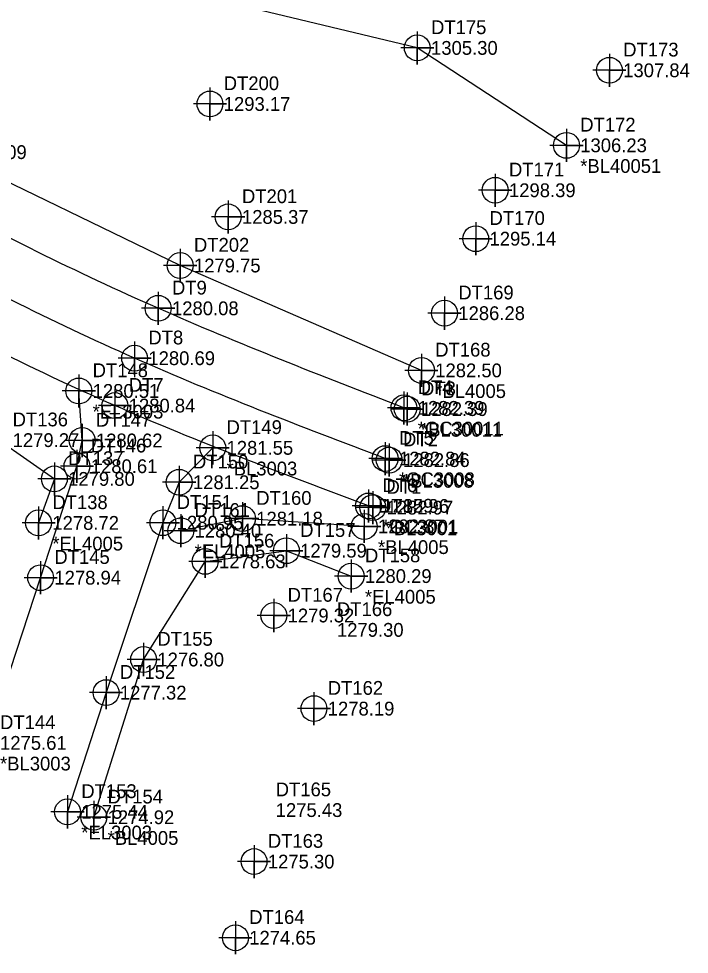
# Model space of a CAD drawing. Extents: x 1391270 to 1392151, y 960049 to 960667.
# Drawn here: x 1391845.8 to 1391967.4, y 960049.1 to 960218.7 of the extents above; entities that cross this region are included whole.
import ezdxf

# ---------------------------------------------------------------- set-up
doc = ezdxf.new("R2010")
doc.units = 0
for name, color, linetype in [('Exist DTM Breakline', 7, 'Continuous'), ('Exist DTM Breakline Cogo Comment', 7, 'Continuous'), ('Exist DTM Breakline Cogo Elevation', 7, 'Continuous'), ('Exist DTM Breakline Cogo Number', 7, 'Continuous'), ('Exist DTM Breakline Cogo Point CELL', 7, 'Continuous'), ('Exist DTM Crownline', 7, 'Continuous'), ('Exist DTM Crownline Cogo Comment', 7, 'Continuous'), ('Exist DTM Crownline Cogo Elevation', 7, 'Continuous'), ('Exist DTM Crownline Cogo Number', 7, 'Continuous'), ('Exist DTM Crownline Cogo Point CELL', 7, 'Continuous'), ('Exist DTM Regular Point CELL', 7, 'Continuous'), ('Exist DTM Regular Point Cogo Elevation', 7, 'Continuous'), ('Exist DTM Regular Point Cogo Number', 7, 'Continuous'), ('Exist Roads EOP', 7, 'Continuous'), ('Exist Roads EOP Cogo Comment', 7, 'Continuous'), ('Exist Roads EOP Cogo Elevation', 7, 'Continuous'), ('Exist Roads EOP Cogo Number', 7, 'Continuous'), ('Exist Roads EOP Cogo Point CELL', 7, 'Continuous'), ('Exist Roads EOP Other', 7, 'Continuous'), ('Exist Roads EOP Other Cogo Comment', 7, 'Continuous'), ('Exist Roads EOP Other Cogo Elevation', 7, 'Continuous'), ('Exist Roads EOP Other Cogo Number', 7, 'Continuous'), ('Exist Roads EOP Other Cogo Point CELL', 7, 'Continuous'), ('Exist Vegetation Shrub Cogo Elevation', 7, 'Continuous'), ('Exist Vegetation Shrub Cogo Number', 7, 'Continuous'), ('Exist Vegetation Tree Cogo Elevation', 7, 'Continuous'), ('Exist Vegetation Tree Cogo Number', 7, 'Continuous')]:
    doc.layers.add(name, color=color, linetype=linetype)

msp = doc.modelspace()

# ---------------------------------------------------------------- linework, layer by layer
at = {"layer": 'Exist DTM Breakline'}
for points in [[(1391945.147, 960195.757), (1391918.09, 960213.421), (1391881.206, 960222.292), (1391849.896, 960235.631), (1391826.517, 960251.571), (1391802.004, 960268.368), (1391783.721, 960280.05), (1391763.211, 960305.363), (1391726.912, 960330.123), (1391710.789, 960346.476), (1391703.438, 960384.306)], [(1391918.848, 960154.955), (1391875.094, 960173.971), (1391832.683, 960194.523), (1391807.232, 960209.528), (1391789.699, 960221.943), (1391750.487, 960246.736), (1391714.022, 960278.792), (1391697.218, 960295.108)], [(1391783.595, 960167.857), (1391809.479, 960158.717), (1391842.214, 960142.313), (1391852.279, 960135.283), (1391849.414, 960127.307)], [(1391908.471, 960126.669), (1391886.387, 960128.086), (1391875.205, 960125.894)], [(1391859.44, 960073.944), (1391868.463, 960102.54), (1391879.641, 960120.333), (1391894.357, 960122.271), (1391906.105, 960117.666)]]:
    msp.add_lwpolyline(points, dxfattribs=at)
at = {"layer": 'Exist DTM Breakline Cogo Point CELL'}
for points in [[(1391918.09, 960216.421), (1391918.09, 960210.421), (1391918.09, 960213.421), (1391921.09, 960213.421), (1391915.09, 960213.421)], [(1391945.147, 960198.757), (1391945.147, 960192.757), (1391945.147, 960195.757), (1391948.147, 960195.757), (1391942.147, 960195.757)], [(1391875.094, 960176.971), (1391875.094, 960170.971), (1391875.094, 960173.971), (1391878.094, 960173.971), (1391872.094, 960173.971)], [(1391918.848, 960157.955), (1391918.848, 960151.955), (1391918.848, 960154.955), (1391921.848, 960154.955), (1391915.848, 960154.955)], [(1391852.279, 960138.283), (1391852.279, 960132.283), (1391852.279, 960135.283), (1391855.279, 960135.283), (1391849.279, 960135.283)], [(1391849.414, 960130.307), (1391849.414, 960124.307), (1391849.414, 960127.307), (1391852.414, 960127.307), (1391846.414, 960127.307)], [(1391886.387, 960131.086), (1391886.387, 960125.086), (1391886.387, 960128.086), (1391889.387, 960128.086), (1391883.387, 960128.086)], [(1391908.471, 960129.669), (1391908.471, 960123.669), (1391908.471, 960126.669), (1391911.471, 960126.669), (1391905.471, 960126.669)], [(1391875.205, 960128.894), (1391875.205, 960122.894), (1391875.205, 960125.894), (1391878.205, 960125.894), (1391872.205, 960125.894)], [(1391894.357, 960125.271), (1391894.357, 960119.271), (1391894.357, 960122.271), (1391897.357, 960122.271), (1391891.357, 960122.271)], [(1391879.641, 960123.333), (1391879.641, 960117.333), (1391879.641, 960120.333), (1391882.641, 960120.333), (1391876.641, 960120.333)], [(1391906.105, 960120.666), (1391906.105, 960114.666), (1391906.105, 960117.666), (1391909.105, 960117.666), (1391903.105, 960117.666)], [(1391868.463, 960105.54), (1391868.463, 960099.54), (1391868.463, 960102.54), (1391871.463, 960102.54), (1391865.463, 960102.54)], [(1391859.44, 960076.944), (1391859.44, 960070.944), (1391859.44, 960073.944), (1391862.44, 960073.944), (1391856.44, 960073.944)]]:
    msp.add_lwpolyline(points, dxfattribs=at)
for centre in [(1391918.09, 960213.421), (1391945.147, 960195.757), (1391875.094, 960173.971), (1391918.848, 960154.955), (1391852.279, 960135.283), (1391849.414, 960127.307), (1391886.387, 960128.086), (1391875.205, 960125.894), (1391908.471, 960126.669), (1391894.357, 960122.271), (1391879.641, 960120.333), (1391906.105, 960117.666), (1391868.463, 960102.54), (1391859.44, 960073.944)]:
    msp.add_circle(centre, 2.344, dxfattribs=at)
at = {"layer": 'Exist DTM Crownline'}
msp.add_line((1391913.011, 960138.693), (1391912.281, 960138.966), dxfattribs=at)
msp.add_spline([(1391912.281, 960138.966), (1391866.83, 960157.169), (1391822.661, 960179.344), (1391780.998, 960205.13), (1391740.996, 960234.086), (1391702.853, 960265.768), (1391666.471, 960297.967)], degree=3, dxfattribs=at)
at = {"layer": 'Exist DTM Crownline Cogo Point CELL'}
for points in [[(1391866.83, 960160.169), (1391866.83, 960154.169), (1391866.83, 960157.169), (1391869.83, 960157.169), (1391863.83, 960157.169)], [(1391912.281, 960141.966), (1391912.281, 960135.966), (1391912.281, 960138.966), (1391915.281, 960138.966), (1391909.281, 960138.966)], [(1391913.011, 960141.693), (1391913.011, 960135.693), (1391913.011, 960138.693), (1391916.011, 960138.693), (1391910.011, 960138.693)]]:
    msp.add_lwpolyline(points, dxfattribs=at)
for centre in [(1391866.83, 960157.169), (1391912.281, 960138.966), (1391913.011, 960138.693)]:
    msp.add_circle(centre, 2.344, dxfattribs=at)
at = {"layer": 'Exist DTM Regular Point CELL'}
for points in [[(1391952.934, 960212.364), (1391952.934, 960206.364), (1391952.934, 960209.364), (1391955.934, 960209.364), (1391949.934, 960209.364)], [(1391880.495, 960206.26), (1391880.495, 960200.26), (1391880.495, 960203.26), (1391883.495, 960203.26), (1391877.495, 960203.26)], [(1391932.223, 960190.612), (1391932.223, 960184.612), (1391932.223, 960187.612), (1391935.223, 960187.612), (1391929.223, 960187.612)], [(1391883.798, 960185.78), (1391883.798, 960179.78), (1391883.798, 960182.78), (1391886.798, 960182.78), (1391880.798, 960182.78)], [(1391928.694, 960181.83), (1391928.694, 960175.83), (1391928.694, 960178.83), (1391931.694, 960178.83), (1391925.694, 960178.83)], [(1391923.036, 960168.326), (1391923.036, 960162.326), (1391923.036, 960165.326), (1391926.036, 960165.326), (1391920.036, 960165.326)], [(1391892.081, 960113.522), (1391892.081, 960107.522), (1391892.081, 960110.522), (1391895.081, 960110.522), (1391889.081, 960110.522)], [(1391899.359, 960096.642), (1391899.359, 960090.642), (1391899.359, 960093.642), (1391902.359, 960093.642), (1391896.359, 960093.642)], [(1391888.493, 960068.907), (1391888.493, 960062.907), (1391888.493, 960065.907), (1391891.493, 960065.907), (1391885.493, 960065.907)], [(1391885.115, 960055.102), (1391885.115, 960049.102), (1391885.115, 960052.102), (1391888.115, 960052.102), (1391882.115, 960052.102)]]:
    msp.add_lwpolyline(points, dxfattribs=at)
for centre in [(1391952.934, 960209.364), (1391880.495, 960203.26), (1391932.223, 960187.612), (1391883.798, 960182.78), (1391928.694, 960178.83), (1391923.036, 960165.326), (1391892.081, 960110.522), (1391899.359, 960093.642), (1391888.493, 960065.907), (1391885.115, 960052.102)]:
    msp.add_circle(centre, 2.344, dxfattribs=at)
at = {"layer": 'Exist Roads EOP'}
for p, q in [((1391916.273, 960147.94), (1391915.673, 960148.156)), ((1391910.019, 960130.083), (1391909.259, 960130.384))]:
    msp.add_line(p, q, dxfattribs=at)
for points in [[(1391915.673, 960148.156), (1391871.111, 960166.209), (1391827.705, 960187.765), (1391786.031, 960213.485), (1391746.988, 960241.829), (1391709.378, 960273.178), (1391672.886, 960305.161)], [(1391909.259, 960130.384), (1391863.262, 960148.577), (1391817.991, 960171.223), (1391775.806, 960197.201), (1391735.389, 960227.09), (1391696.713, 960258.946), (1391660.088, 960291.389)]]:
    msp.add_spline(points, degree=3, dxfattribs=at)
at = {"layer": 'Exist Roads EOP Cogo Point CELL'}
for points in [[(1391871.111, 960169.209), (1391871.111, 960163.209), (1391871.111, 960166.209), (1391874.111, 960166.209), (1391868.111, 960166.209)], [(1391863.262, 960151.577), (1391863.262, 960145.577), (1391863.262, 960148.577), (1391866.262, 960148.577), (1391860.262, 960148.577)], [(1391915.673, 960151.156), (1391915.673, 960145.156), (1391915.673, 960148.156), (1391918.673, 960148.156), (1391912.673, 960148.156)], [(1391916.273, 960150.94), (1391916.273, 960144.94), (1391916.273, 960147.94), (1391919.273, 960147.94), (1391913.273, 960147.94)], [(1391909.259, 960133.384), (1391909.259, 960127.384), (1391909.259, 960130.384), (1391912.259, 960130.384), (1391906.259, 960130.384)], [(1391910.019, 960133.083), (1391910.019, 960127.083), (1391910.019, 960130.083), (1391913.019, 960130.083), (1391907.019, 960130.083)]]:
    msp.add_lwpolyline(points, dxfattribs=at)
for centre in [(1391871.111, 960166.209), (1391863.262, 960148.577), (1391915.673, 960148.156), (1391916.273, 960147.94), (1391909.259, 960130.384), (1391910.019, 960130.083)]:
    msp.add_circle(centre, 2.344, dxfattribs=at)
at = {"layer": 'Exist Roads EOP Other'}
for points in [[(1391839.93, 960087.426), (1391849.786, 960117.376), (1391856.383, 960137.584), (1391857.314, 960142.252), (1391856.722, 960151.227)], [(1391881.003, 960140.916), (1391874.905, 960134.676), (1391871.97, 960127.346), (1391861.66, 960096.537), (1391854.663, 960074.923)]]:
    msp.add_lwpolyline(points, dxfattribs=at)
at = {"layer": 'Exist Roads EOP Other Cogo Point CELL'}
for points in [[(1391856.722, 960154.227), (1391856.722, 960148.227), (1391856.722, 960151.227), (1391859.722, 960151.227), (1391853.722, 960151.227)], [(1391857.314, 960145.252), (1391857.314, 960139.252), (1391857.314, 960142.252), (1391860.314, 960142.252), (1391854.314, 960142.252)], [(1391881.003, 960143.916), (1391881.003, 960137.916), (1391881.003, 960140.916), (1391884.003, 960140.916), (1391878.003, 960140.916)], [(1391856.383, 960140.584), (1391856.383, 960134.584), (1391856.383, 960137.584), (1391859.383, 960137.584), (1391853.383, 960137.584)], [(1391874.905, 960137.676), (1391874.905, 960131.676), (1391874.905, 960134.676), (1391877.905, 960134.676), (1391871.905, 960134.676)], [(1391871.97, 960130.346), (1391871.97, 960124.346), (1391871.97, 960127.346), (1391874.97, 960127.346), (1391868.97, 960127.346)], [(1391849.786, 960120.376), (1391849.786, 960114.376), (1391849.786, 960117.376), (1391852.786, 960117.376), (1391846.786, 960117.376)], [(1391861.66, 960099.537), (1391861.66, 960093.537), (1391861.66, 960096.537), (1391864.66, 960096.537), (1391858.66, 960096.537)], [(1391854.663, 960077.923), (1391854.663, 960071.923), (1391854.663, 960074.923), (1391857.663, 960074.923), (1391851.663, 960074.923)]]:
    msp.add_lwpolyline(points, dxfattribs=at)
for centre in [(1391856.722, 960151.227), (1391857.314, 960142.252), (1391881.003, 960140.916), (1391856.383, 960137.584), (1391874.905, 960134.676), (1391871.97, 960127.346), (1391849.786, 960117.376), (1391861.66, 960096.537), (1391854.663, 960074.923)]:
    msp.add_circle(centre, 2.344, dxfattribs=at)

# ---------------------------------------------------------------- texts
at = {"layer": 'Exist DTM Breakline Cogo Comment'}
for s, p in [('*BL40051', (1391947.647, 960190.757)), ('*BL4005', (1391921.348, 960149.955)), ('*EL4005', (1391851.914, 960122.307)), ('*EL4005', (1391877.705, 960120.894)), ('*BL4005', (1391910.971, 960121.669)), ('*EL4005', (1391908.605, 960112.666)), ('*BL4005', (1391861.94, 960068.944))]:
    msp.add_text(s, height=2.5, dxfattribs=at).set_placement(p)
at = {"layer": 'Exist DTM Breakline Cogo Elevation'}
for s, p in [('1305.30', (1391920.59, 960212.171)), ('1277.09', (1391835.183, 960193.273)), ('1306.23', (1391947.647, 960194.507)), ('1279.75', (1391877.594, 960172.721)), ('1282.50', (1391921.348, 960153.705)), ('1279.27', (1391844.714, 960141.063)), ('1279.80', (1391854.779, 960134.033)), ('1278.72', (1391851.914, 960126.057)), ('1281.18', (1391888.887, 960126.836)), ('1282.87', (1391910.971, 960125.419)), ('1280.40', (1391877.705, 960124.644)), ('1279.59', (1391896.857, 960121.021)), ('1278.63', (1391882.141, 960119.083)), ('1280.29', (1391908.605, 960116.416)), ('1276.80', (1391870.963, 960101.29)), ('1274.92', (1391861.94, 960072.694))]:
    msp.add_text(s, height=2.5, dxfattribs=at).set_placement(p)
at = {"layer": 'Exist DTM Breakline Cogo Number'}
for s, p in [('DT175', (1391920.59, 960215.921)), ('DT172', (1391947.647, 960198.257)), ('DT202', (1391877.594, 960176.471)), ('DT168', (1391921.348, 960157.455)), ('DT136', (1391844.714, 960144.813)), ('DT137', (1391854.779, 960137.783)), ('DT160', (1391888.887, 960130.586)), ('DT138', (1391851.914, 960129.807)), ('DT159', (1391910.971, 960129.169)), ('DT161', (1391877.705, 960128.394)), ('DT157', (1391896.857, 960124.771)), ('DT156', (1391882.141, 960122.833)), ('DT158', (1391908.605, 960120.166)), ('DT155', (1391870.963, 960105.04)), ('DT154', (1391861.94, 960076.444))]:
    msp.add_text(s, height=2.5, dxfattribs=at).set_placement(p)
at = {"layer": 'Exist DTM Crownline Cogo Comment'}
for s, p in [('*OC3008', (1391914.781, 960133.966)), ('*BL3008', (1391915.511, 960133.693))]:
    msp.add_text(s, height=2.5, dxfattribs=at).set_placement(p)
at = {"layer": 'Exist DTM Crownline Cogo Elevation'}
for s, p in [('1280.69', (1391869.33, 960155.919)), ('1282.84', (1391914.781, 960137.716)), ('1282.86', (1391915.511, 960137.443))]:
    msp.add_text(s, height=2.5, dxfattribs=at).set_placement(p)
at = {"layer": 'Exist DTM Crownline Cogo Number'}
for s, p in [('DT8', (1391869.33, 960159.669)), ('DT5', (1391914.781, 960141.466)), ('DT2', (1391915.511, 960141.193))]:
    msp.add_text(s, height=2.5, dxfattribs=at).set_placement(p)
at = {"layer": 'Exist DTM Regular Point Cogo Elevation'}
for s, p in [('1307.84', (1391955.434, 960208.114)), ('1293.17', (1391882.995, 960202.01)), ('1298.39', (1391934.723, 960186.362)), ('1285.37', (1391886.298, 960181.53)), ('1295.14', (1391931.194, 960177.58)), ('1286.28', (1391925.536, 960164.076)), ('1278.19', (1391901.859, 960092.392)), ('1275.30', (1391890.993, 960064.657)), ('1274.65', (1391887.615, 960050.852))]:
    msp.add_text(s, height=2.5, dxfattribs=at).set_placement(p)
at = {"layer": 'Exist DTM Regular Point Cogo Number'}
for s, p in [('DT173', (1391955.434, 960211.864)), ('DT200', (1391882.995, 960205.76)), ('DT171', (1391934.723, 960190.112)), ('DT201', (1391886.298, 960185.28)), ('DT170', (1391931.194, 960181.33)), ('DT169', (1391925.536, 960167.826)), ('DT162', (1391901.859, 960096.142)), ('DT163', (1391890.993, 960068.407)), ('DT164', (1391887.615, 960054.602))]:
    msp.add_text(s, height=2.5, dxfattribs=at).set_placement(p)
at = {"layer": 'Exist Roads EOP Cogo Comment'}
for s, p in [('*OC30011', (1391918.173, 960143.156)), ('*BL30011', (1391918.773, 960142.94)), ('*OC3001', (1391911.759, 960125.384)), ('*BL3001', (1391912.519, 960125.083))]:
    msp.add_text(s, height=2.5, dxfattribs=at).set_placement(p)
at = {"layer": 'Exist Roads EOP Cogo Elevation'}
for s, p in [('1280.08', (1391873.611, 960164.959)), ('1280.84', (1391865.762, 960147.327)), ('1282.39', (1391918.173, 960146.906)), ('1282.39', (1391918.773, 960146.69)), ('1282.96', (1391911.759, 960129.134)), ('1282.97', (1391912.519, 960128.833))]:
    msp.add_text(s, height=2.5, dxfattribs=at).set_placement(p)
at = {"layer": 'Exist Roads EOP Cogo Number'}
for s, p in [('DT9', (1391873.611, 960168.709)), ('DT7', (1391865.762, 960151.077)), ('DT4', (1391918.173, 960150.656)), ('DT3', (1391918.773, 960150.44)), ('DT6', (1391911.759, 960132.884)), ('DT1', (1391912.519, 960132.583))]:
    msp.add_text(s, height=2.5, dxfattribs=at).set_placement(p)
at = {"layer": 'Exist Roads EOP Other Cogo Comment'}
for s, p in [('*EL3003', (1391859.222, 960146.227)), ('*BL3003', (1391883.503, 960135.916)), ('*BL3003', (1391842.43, 960082.426)), ('*EL3003', (1391857.163, 960069.923))]:
    msp.add_text(s, height=2.5, dxfattribs=at).set_placement(p)
at = {"layer": 'Exist Roads EOP Other Cogo Elevation'}
for s, p in [('1280.51', (1391859.222, 960149.977)), ('1280.62', (1391859.814, 960141.002)), ('1281.55', (1391883.503, 960139.666)), ('1280.61', (1391858.883, 960136.334)), ('1281.25', (1391877.405, 960133.426)), ('1280.95', (1391874.47, 960126.096)), ('1278.94', (1391852.286, 960116.126)), ('1277.32', (1391864.16, 960095.287)), ('1275.61', (1391842.43, 960086.176)), ('1275.44', (1391857.163, 960073.673))]:
    msp.add_text(s, height=2.5, dxfattribs=at).set_placement(p)
at = {"layer": 'Exist Roads EOP Other Cogo Number'}
for s, p in [('DT148', (1391859.222, 960153.727)), ('DT147', (1391859.814, 960144.752)), ('DT149', (1391883.503, 960143.416)), ('DT146', (1391858.883, 960140.084)), ('DT150', (1391877.405, 960137.176)), ('DT151', (1391874.47, 960129.846)), ('DT145', (1391852.286, 960119.876)), ('DT152', (1391864.16, 960099.037)), ('DT144', (1391842.43, 960089.926)), ('DT153', (1391857.163, 960077.423))]:
    msp.add_text(s, height=2.5, dxfattribs=at).set_placement(p)
at = {"layer": 'Exist Vegetation Shrub Cogo Elevation'}
for s, p in [('1279.32', (1391894.581, 960109.272)), ('1279.30', (1391903.528, 960106.666))]:
    msp.add_text(s, height=2.5, dxfattribs=at).set_placement(p)
at = {"layer": 'Exist Vegetation Shrub Cogo Number'}
for s, p in [('DT167', (1391894.581, 960113.022)), ('DT166', (1391903.528, 960110.416))]:
    msp.add_text(s, height=2.5, dxfattribs=at).set_placement(p)
at = {"layer": 'Exist Vegetation Tree Cogo Elevation'}
msp.add_text('1275.43', height=2.5, dxfattribs=at).set_placement((1391892.419, 960073.994))
at = {"layer": 'Exist Vegetation Tree Cogo Number'}
msp.add_text('DT165', height=2.5, dxfattribs=at).set_placement((1391892.419, 960077.744))

doc.saveas('drawing.dxf')
